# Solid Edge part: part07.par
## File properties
Author: CADCIM
Template: Normal.par
Last saved by: CADCIM
Revision: 4
Application: Solid Edge
Accuracy: 0.99
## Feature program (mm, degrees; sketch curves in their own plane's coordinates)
sketch for "unnamed Protrusion 1" #1 plane through (0, 0, 0) normal (0, 0, 1) x-axis (1, 0, 0)
  circle centre (17.5, 12.5) radius 2.5
sketch for "unnamed Protrusion 1" #2 plane through (0, 0, 0) normal (0, 0, 1) x-axis (1, 0, 0)
  circle centre (17.5, -12.5) radius 2.5
sketch for "unnamed Protrusion 1" #3 plane through (0, 0, 0) normal (0, 0, 1) x-axis (1, 0, 0)
  line (-17.5, 2.5) -> (-22.5, 2.5)
  line (-22.5, 2.5) -> (-22.5, 5.5)
  arc centre (-20.5, 5.5) radius 2 from (-22.5, 5.5) to (-20.5, 7.5) cw
  line (-20.5, 7.5) -> (10.5, 7.5)
  arc centre (10.5, 9.5) radius 2 from (10.5, 7.5) to (12.5, 9.5) ccw
  line (12.5, 9.5) -> (12.5, 12.5)
  arc centre (17.5, 12.5) radius 5 from (12.5, 12.5) to (22.5, 12.5) cw
  line (22.5, 12.5) -> (22.5, -12.5)
  arc centre (17.5, -12.5) radius 5 from (12.5, -12.5) to (22.5, -12.5) ccw
  line (12.5, -9.5) -> (12.5, -12.5)
  arc centre (10.5, -9.5) radius 2 from (10.5, -7.5) to (12.5, -9.5) cw
  line (-20.5, -7.5) -> (10.5, -7.5)
  arc centre (-20.5, -5.5) radius 2 from (-22.5, -5.5) to (-20.5, -7.5) ccw
  line (-22.5, -2.5) -> (-22.5, -5.5)
  line (-17.5, -2.5) -> (-22.5, -2.5)
  arc centre (-17.5, 0) radius 2.5 from (-17.5, 2.5) to (-17.5, -2.5) cw
  dimension (linear) = 22.5
  dimension (linear) = 17.5
extrude "unnamed Protrusion 1" add finite 5 along +normal
sketch for "ExtrudedProtrusion_2" #1 plane through (6.5901, 0, 20.9099) normal (0.707107, 0, 0.707107) x-axis (0, 1, 0)
  circle centre (0, -5.5) radius 3.75
sketch for "ExtrudedProtrusion_2" #2 plane through (6.5901, 0, 20.9099) normal (0.707107, 0, 0.707107) x-axis (0, 1, 0)
  line (-7.5, -22.5) -> (-7.5, -5.5)
  arc centre (0, -5.5) radius 7.5 from (7.5, -5.5) to (-7.5, -5.5) ccw
  line (7.5, -5.5) -> (7.5, -22.5)
  line (7.5, -22.5) -> (-7.5, -22.5)
  dimension (linear) = 7.5
extrude "ExtrudedProtrusion_2" add through along -normal
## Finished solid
Body 1: solid body, 26 faces, 64 edges, 38 vertices.
  Faces by surface: plane 15, cylinder 11
  Edges by curve: line 42, circle 20, ellipse 2
Bounding box of the edges (mm): 45.000 x 35.000 x 22.324, from (-22.5, -17.5, 0) to (22.5, 17.5, 22.3241).
Cylindrical faces by radius (mm): R2 x4, R2.5 x3, R3.75 x1, R5 x2, R7.5 x1
Planar faces by outward normal: +x 1, +y 2, +z 4, -x 4, -y 2, -z 1, oblique 1
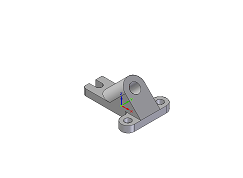
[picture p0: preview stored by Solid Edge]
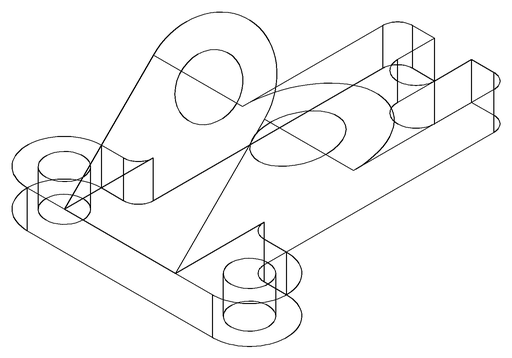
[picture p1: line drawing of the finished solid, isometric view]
